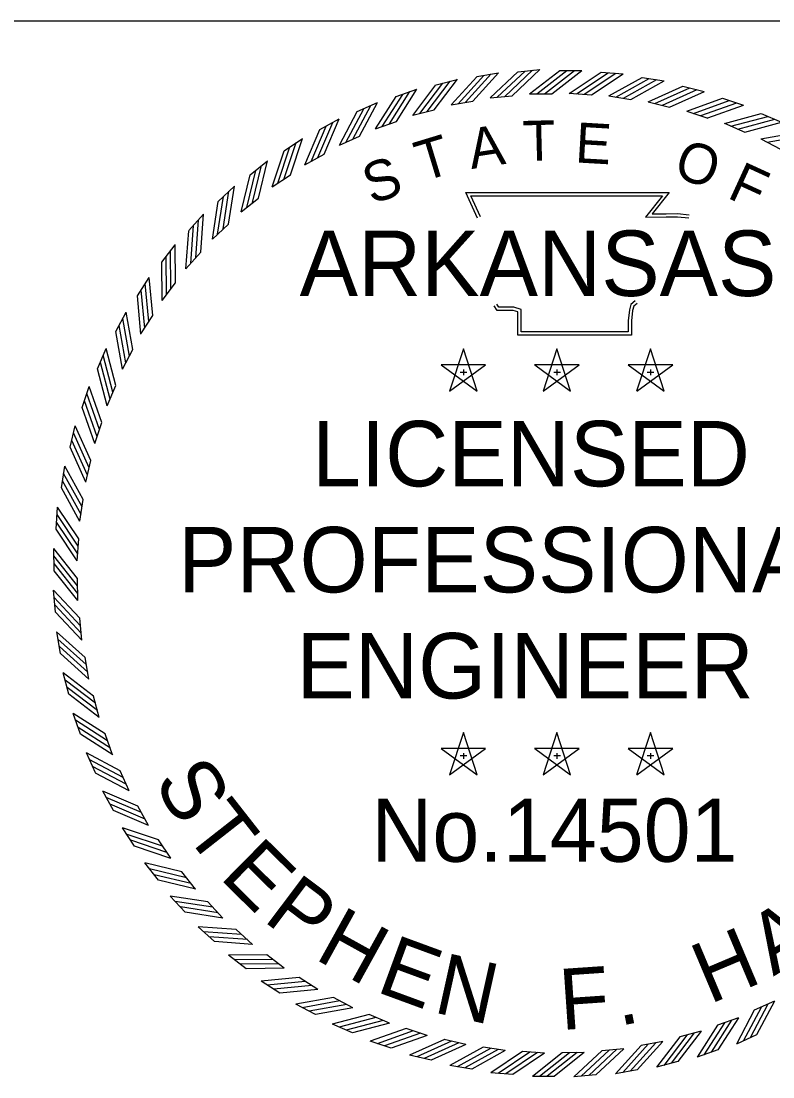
# Model space of a CAD drawing. Extents: x 16 to 1228740, y 11 to 152440.
# Drawn here: x 17.6694 to 17.7979, y 10.8182 to 10.9986 of the extents above; entities that cross this region are included whole.
import ezdxf

# ---------------------------------------------------------------- set-up
doc = ezdxf.new("R2010")
doc.units = 0
doc.layers.add('R_No Plot', color=7, linetype='Continuous')
doc.layers.add('STAMP_FRED', color=7, linetype='Continuous')

msp = doc.modelspace()

# ---------------------------------------------------------------- linework, layer by layer
at = {"layer": 'R_No Plot'}
msp.add_line((17.888, 10.99864), (17.47349, 10.99864), dxfattribs=at)
at = {"layer": 'STAMP_FRED'}
for p, q in [((17.75431, 10.98999), (17.75806, 10.99034)), ((17.74029, 10.98773), (17.74393, 10.98868)), ((17.74725, 10.98915), (17.75096, 10.9898)), ((17.76145, 10.9902), (17.76522, 10.9902)), ((17.76851, 10.98992), (17.77227, 10.98964)), ((17.77555, 10.989), (17.77928, 10.98842)), ((17.73347, 10.98573), (17.73702, 10.98699)), ((17.7825, 10.98751), (17.78616, 10.98662)), ((17.74288, 10.9843), (17.7466, 10.98496)), ((17.74955, 10.98553), (17.75332, 10.98587)), ((17.7563, 10.98619), (17.76008, 10.98619)), ((17.76308, 10.9863), (17.76685, 10.98602)), ((17.76985, 10.98584), (17.77358, 10.98525)), ((17.7893, 10.98545), (17.79288, 10.98426)), ((17.72683, 10.98318), (17.73027, 10.98473)), ((17.73633, 10.98254), (17.73999, 10.9835)), ((17.77655, 10.98483), (17.78023, 10.98394)), ((17.78315, 10.98327), (17.78674, 10.98207)), ((17.72043, 10.9801), (17.72373, 10.98192)), ((17.72996, 10.98024), (17.73352, 10.9815)), ((17.79591, 10.98283), (17.79938, 10.98135)), ((17.7896, 10.98117), (17.79308, 10.97968)), ((17.71431, 10.97649), (17.71745, 10.97858)), ((17.72379, 10.97742), (17.72723, 10.97896)), ((17.79585, 10.97854), (17.79919, 10.97677)), ((17.71787, 10.97409), (17.72118, 10.97592)), ((17.70851, 10.97239), (17.71146, 10.97473)), ((17.71226, 10.9703), (17.7154, 10.97239)), ((17.70306, 10.96782), (17.70581, 10.9704)), ((17.70697, 10.96605), (17.70993, 10.9684)), ((17.69801, 10.96283), (17.70054, 10.96562)), ((17.70205, 10.96138), (17.70481, 10.96396)), ((17.69339, 10.95743), (17.69568, 10.96042)), ((17.69754, 10.95632), (17.70007, 10.95912)), ((17.68923, 10.95166), (17.69126, 10.95484)), ((17.69346, 10.9509), (17.69575, 10.95391)), ((17.68556, 10.94558), (17.68733, 10.94891)), ((17.68984, 10.94517), (17.69187, 10.94835)), ((17.68241, 10.93921), (17.68389, 10.94268)), ((17.6867, 10.93915), (17.68847, 10.94249)), ((17.74497, 10.94264), (17.74261, 10.9354)), ((17.74732, 10.93541), (17.74498, 10.94265)), ((17.76096, 10.94264), (17.7586, 10.9354)), ((17.76331, 10.93541), (17.76097, 10.94265)), ((17.77695, 10.94264), (17.77459, 10.9354)), ((17.7793, 10.93541), (17.77696, 10.94265)), ((17.74877, 10.93988), (17.74116, 10.93988)), ((17.74117, 10.93988), (17.74732, 10.9354)), ((17.74262, 10.93541), (17.74878, 10.93987)), ((17.76476, 10.93988), (17.75715, 10.93988)), ((17.75716, 10.93988), (17.76331, 10.9354)), ((17.75861, 10.93541), (17.76477, 10.93987)), ((17.78076, 10.93988), (17.77315, 10.93988)), ((17.77315, 10.93988), (17.7793, 10.9354)), ((17.7746, 10.93541), (17.78076, 10.93987)), ((17.74443, 10.93866), (17.74556, 10.93866)), ((17.74498, 10.93907), (17.74498, 10.93811)), ((17.76042, 10.93866), (17.76155, 10.93866)), ((17.76097, 10.93907), (17.76097, 10.93811)), ((17.77641, 10.93866), (17.77754, 10.93866)), ((17.77696, 10.93907), (17.77696, 10.93811)), ((17.67979, 10.9326), (17.68098, 10.93618)), ((17.68407, 10.9329), (17.68556, 10.93638)), ((17.67773, 10.9258), (17.67862, 10.92947)), ((17.68197, 10.92645), (17.68317, 10.93004)), ((17.68041, 10.91985), (17.6813, 10.92353)), ((17.67624, 10.91885), (17.67682, 10.92258)), ((17.6794, 10.91315), (17.67999, 10.91688)), ((17.67532, 10.91181), (17.6756, 10.91557)), ((17.67894, 10.90638), (17.67922, 10.91015)), ((17.67499, 10.90471), (17.67496, 10.90848)), ((17.67905, 10.8996), (17.67902, 10.90338)), ((17.67525, 10.89761), (17.6749, 10.90136)), ((17.67972, 10.89285), (17.67937, 10.89662)), ((17.67609, 10.89055), (17.67544, 10.89426)), ((17.68094, 10.88618), (17.68028, 10.8899)), ((17.67751, 10.88359), (17.67656, 10.88724)), ((17.6827, 10.87963), (17.68174, 10.88329)), ((17.67951, 10.87677), (17.67825, 10.88032)), ((17.685, 10.87326), (17.68375, 10.87682)), ((17.74497, 10.87707), (17.74261, 10.86984)), ((17.74732, 10.86984), (17.74498, 10.87708)), ((17.76096, 10.87707), (17.7586, 10.86984)), ((17.76331, 10.86984), (17.76097, 10.87708)), ((17.77695, 10.87707), (17.77459, 10.86984)), ((17.7793, 10.86984), (17.77696, 10.87708)), ((17.68206, 10.87014), (17.68051, 10.87357)), ((17.74877, 10.87431), (17.74116, 10.87432)), ((17.74117, 10.87431), (17.74732, 10.86983)), ((17.74262, 10.86984), (17.74878, 10.87431)), ((17.74443, 10.8731), (17.74556, 10.8731)), ((17.74498, 10.8735), (17.74498, 10.87255)), ((17.76476, 10.87431), (17.75715, 10.87432)), ((17.75716, 10.87431), (17.76331, 10.86983)), ((17.75861, 10.86984), (17.76477, 10.87431)), ((17.76042, 10.8731), (17.76155, 10.8731)), ((17.76097, 10.8735), (17.76097, 10.87255)), ((17.78076, 10.87431), (17.77315, 10.87432)), ((17.77315, 10.87431), (17.7793, 10.86983)), ((17.7746, 10.86984), (17.78076, 10.87431)), ((17.77641, 10.8731), (17.77754, 10.8731)), ((17.77696, 10.8735), (17.77696, 10.87255)), ((17.68783, 10.86709), (17.68628, 10.87053)), ((17.68515, 10.86374), (17.68332, 10.86703)), ((17.69115, 10.86118), (17.68932, 10.86448)), ((17.68875, 10.85761), (17.68666, 10.86075)), ((17.69494, 10.85556), (17.69285, 10.8587)), ((17.69285, 10.85181), (17.69051, 10.85476)), ((17.69919, 10.85027), (17.69684, 10.85323)), ((17.69742, 10.84636), (17.69484, 10.84911)), ((17.70386, 10.84535), (17.70128, 10.84811)), ((17.70242, 10.84131), (17.69962, 10.84384)), ((17.70892, 10.84084), (17.70612, 10.84337)), ((17.70781, 10.83669), (17.70482, 10.83898)), ((17.71434, 10.83676), (17.71134, 10.83905)), ((17.72007, 10.83314), (17.71689, 10.83517)), ((17.71358, 10.83253), (17.7104, 10.83456)), ((17.72609, 10.83), (17.72275, 10.83177)), ((17.71966, 10.82886), (17.71633, 10.83063)), ((17.79815, 10.83113), (17.79471, 10.82958)), ((17.73234, 10.82738), (17.72886, 10.82886)), ((17.79199, 10.82831), (17.78842, 10.82705)), ((17.72603, 10.82571), (17.72257, 10.82719)), ((17.73879, 10.82527), (17.7352, 10.82647)), ((17.74539, 10.82371), (17.74171, 10.82461)), ((17.78561, 10.826), (17.78195, 10.82504)), ((17.79511, 10.82536), (17.79167, 10.82381)), ((17.73264, 10.82309), (17.72906, 10.82428)), ((17.75209, 10.8227), (17.74836, 10.82329)), ((17.75886, 10.82224), (17.75509, 10.82252)), ((17.77239, 10.82302), (17.76863, 10.82267)), ((17.77906, 10.82424), (17.77534, 10.82358)), ((17.78847, 10.82281), (17.78492, 10.82155)), ((17.73944, 10.82103), (17.73578, 10.82192)), ((17.76564, 10.82235), (17.76186, 10.82232)), ((17.78165, 10.82082), (17.77801, 10.81986)), ((17.74639, 10.81954), (17.74266, 10.82012)), ((17.75343, 10.81862), (17.74967, 10.8189)), ((17.77469, 10.81939), (17.77098, 10.81874)), ((17.76053, 10.81829), (17.75676, 10.81826)), ((17.76763, 10.81855), (17.76388, 10.8182))]:
    msp.add_line(p, q, dxfattribs=at)
for points in [[(17.75331, 10.98587), (17.75806, 10.99034)], [(17.73998, 10.9835), (17.74394, 10.98869)], [(17.74288, 10.9843), (17.74725, 10.98914)], [(17.74407, 10.9845), (17.74844, 10.98934)], [(17.74536, 10.98476), (17.74973, 10.9896)], [(17.7466, 10.98496), (17.75097, 10.98981)], [(17.74955, 10.98552), (17.7543, 10.98999)], [(17.75076, 10.98562), (17.75551, 10.99009)], [(17.75206, 10.98577), (17.75681, 10.99024)], [(17.7563, 10.98619), (17.76144, 10.9902)], [(17.75751, 10.98618), (17.76265, 10.99019)], [(17.75882, 10.9862), (17.76396, 10.99022)], [(17.76008, 10.98619), (17.76522, 10.9902)], [(17.76308, 10.98629), (17.7685, 10.98992)], [(17.76429, 10.98619), (17.76971, 10.98982)], [(17.7656, 10.98613), (17.77102, 10.98975)], [(17.76685, 10.98602), (17.77227, 10.98964)], [(17.76984, 10.98584), (17.77555, 10.989)], [(17.77104, 10.98564), (17.77675, 10.9888)], [(17.77234, 10.98546), (17.77804, 10.98863)], [(17.73351, 10.9815), (17.73702, 10.98699)], [(17.73633, 10.98253), (17.74028, 10.98772)], [(17.73751, 10.98283), (17.74146, 10.98802)], [(17.73877, 10.98319), (17.74272, 10.98838)], [(17.77358, 10.98526), (17.77928, 10.98842)], [(17.77655, 10.98483), (17.7825, 10.98751)], [(17.77773, 10.98453), (17.78367, 10.98721)], [(17.779, 10.98425), (17.78495, 10.98693)], [(17.72995, 10.98023), (17.73346, 10.98573)], [(17.7311, 10.98063), (17.73461, 10.98612)], [(17.73232, 10.98109), (17.73584, 10.98659)], [(17.78022, 10.98394), (17.78617, 10.98662)], [(17.78315, 10.98327), (17.7893, 10.98545)], [(17.7843, 10.98287), (17.79044, 10.98505)], [(17.72379, 10.97741), (17.72683, 10.98318)], [(17.7249, 10.9779), (17.72794, 10.98367)], [(17.72608, 10.97846), (17.72912, 10.98423)], [(17.72723, 10.97897), (17.73028, 10.98473)], [(17.78555, 10.98249), (17.7917, 10.98467)], [(17.78674, 10.98208), (17.79288, 10.98426)], [(17.72007, 10.97533), (17.72263, 10.98133)], [(17.72118, 10.97592), (17.72374, 10.98192)], [(17.7896, 10.98116), (17.7959, 10.98283)], [(17.79071, 10.98068), (17.79701, 10.98234)], [(17.79192, 10.98019), (17.79823, 10.98185)], [(17.79307, 10.97968), (17.79938, 10.98135)], [(17.71787, 10.97409), (17.72043, 10.98009)], [(17.71894, 10.97467), (17.7215, 10.98067)], [(17.79585, 10.97854), (17.80227, 10.97968)], [(17.71434, 10.97171), (17.7164, 10.9779)], [(17.71539, 10.97239), (17.71745, 10.97858)], [(17.79692, 10.97796), (17.80334, 10.9791)], [(17.71225, 10.97029), (17.71431, 10.97648)], [(17.71327, 10.97096), (17.71532, 10.97715)], [(17.70992, 10.9684), (17.71146, 10.97474)], [(17.70697, 10.96604), (17.70851, 10.97238)], [(17.70793, 10.96679), (17.70946, 10.97313)], [(17.70893, 10.96763), (17.71047, 10.97396)], [(17.70294, 10.9622), (17.70395, 10.96864)], [(17.70388, 10.96311), (17.70489, 10.96956)], [(17.7048, 10.96396), (17.70581, 10.97041)], [(17.7474, 10.96497), (17.74539, 10.96932), (17.78016, 10.96934), (17.77725, 10.96569), (17.77962, 10.96572), (17.78159, 10.96575), (17.78356, 10.96553)], [(17.7479, 10.9652), (17.74625, 10.96877), (17.77902, 10.96879), (17.7761, 10.96513), (17.77962, 10.96517), (17.78156, 10.9652), (17.7835, 10.96499)], [(17.70205, 10.96137), (17.70306, 10.96782)], [(17.70007, 10.95912), (17.70054, 10.96563)], [(17.69836, 10.95721), (17.69883, 10.96371)], [(17.69922, 10.9582), (17.69969, 10.9647)], [(17.69754, 10.95631), (17.69801, 10.96282)], [(17.69574, 10.9539), (17.69568, 10.96043)], [(17.6942, 10.95185), (17.69414, 10.95838)], [(17.69497, 10.95291), (17.69491, 10.95944)], [(17.69346, 10.9509), (17.69339, 10.95742)], [(17.69187, 10.94835), (17.69126, 10.95484)], [(17.6905, 10.94618), (17.6899, 10.95267)], [(17.69118, 10.9473), (17.69058, 10.95379)], [(17.68984, 10.94516), (17.68923, 10.95166)], [(17.77433, 10.95083), (17.7736, 10.95023), (17.77335, 10.9493), (17.77314, 10.94742), (17.77314, 10.94554), (17.75484, 10.94554), (17.75484, 10.94824), (17.75484, 10.94936), (17.75358, 10.94975), (17.75104, 10.94975), (17.75071, 10.95025)], [(17.68847, 10.94249), (17.68733, 10.94891)], [(17.77468, 10.9504), (17.77409, 10.94992), (17.77389, 10.9492), (17.77369, 10.94739), (17.77369, 10.94499), (17.75429, 10.94499), (17.75429, 10.94824), (17.75429, 10.94896), (17.7535, 10.9492), (17.75074, 10.9492), (17.75025, 10.94995)], [(17.68787, 10.94139), (17.68673, 10.94781)], [(17.6867, 10.93915), (17.68556, 10.94557)], [(17.68728, 10.94022), (17.68614, 10.94664)], [(17.68556, 10.93637), (17.68389, 10.94268)], [(17.68456, 10.93401), (17.6829, 10.94031)], [(17.68505, 10.93522), (17.68339, 10.94153)], [(17.68408, 10.9329), (17.68241, 10.9392)], [(17.68316, 10.93004), (17.68098, 10.93618)], [(17.68276, 10.92885), (17.68057, 10.935)], [(17.68197, 10.92645), (17.67979, 10.9326)], [(17.68237, 10.9276), (17.68019, 10.93374)], [(17.6813, 10.92352), (17.67862, 10.92947)], [(17.68099, 10.92231), (17.67831, 10.92825)], [(17.68041, 10.91985), (17.67773, 10.9258)], [(17.68071, 10.92103), (17.67803, 10.92697)], [(17.67998, 10.91688), (17.67682, 10.92258)], [(17.6796, 10.91434), (17.67644, 10.92005)], [(17.67978, 10.91564), (17.67661, 10.92134)], [(17.6794, 10.91314), (17.67624, 10.91885)], [(17.67922, 10.91015), (17.6756, 10.91557)], [(17.67905, 10.90759), (17.67542, 10.91301)], [(17.67912, 10.9089), (17.67549, 10.91432)], [(17.67895, 10.90638), (17.67532, 10.9118)], [(17.67901, 10.90338), (17.67495, 10.90848)], [(17.67901, 10.90212), (17.67495, 10.90723)], [(17.67905, 10.90081), (17.675, 10.90592)], [(17.67905, 10.8996), (17.675, 10.9047)], [(17.67937, 10.89661), (17.6749, 10.90136)], [(17.67947, 10.89536), (17.675, 10.90011)], [(17.67962, 10.89406), (17.67515, 10.89881)], [(17.67972, 10.89285), (17.67525, 10.8976)], [(17.68028, 10.8899), (17.67543, 10.89427)], [(17.68048, 10.88866), (17.67564, 10.89303)], [(17.68074, 10.88738), (17.6759, 10.89174)], [(17.68094, 10.88618), (17.6761, 10.89055)], [(17.68174, 10.88328), (17.67655, 10.88724)], [(17.68205, 10.88207), (17.67686, 10.88602)], [(17.68241, 10.88081), (17.67722, 10.88476)], [(17.68271, 10.87963), (17.67752, 10.88359)], [(17.68374, 10.87681), (17.67825, 10.88032)], [(17.68415, 10.87563), (17.67865, 10.87914)], [(17.68462, 10.8744), (17.67912, 10.87791)], [(17.68501, 10.87325), (17.67951, 10.87676)], [(17.68628, 10.87053), (17.68051, 10.87358)], [(17.68678, 10.86938), (17.68101, 10.87243)], [(17.68734, 10.8682), (17.68158, 10.87124)], [(17.68783, 10.86709), (17.68206, 10.87013)], [(17.68932, 10.86448), (17.68332, 10.86704)], [(17.68991, 10.86337), (17.68391, 10.86593)], [(17.69057, 10.86224), (17.68457, 10.8648)], [(17.69115, 10.86117), (17.68515, 10.86373)], [(17.69285, 10.8587), (17.68666, 10.86075)], [(17.69353, 10.85764), (17.68734, 10.8597)], [(17.69428, 10.85657), (17.68809, 10.85863)], [(17.69495, 10.85555), (17.68876, 10.85761)], [(17.69684, 10.85323), (17.6905, 10.85476)], [(17.69762, 10.85223), (17.69128, 10.85377)], [(17.69845, 10.85123), (17.69211, 10.85276)], [(17.6992, 10.85027), (17.69286, 10.85181)], [(17.70128, 10.8481), (17.69483, 10.84911)], [(17.70213, 10.84718), (17.69568, 10.84819)], [(17.70305, 10.84624), (17.6966, 10.84725)], [(17.70387, 10.84535), (17.69742, 10.84636)], [(17.70612, 10.84337), (17.69961, 10.84384)], [(17.70704, 10.84252), (17.70054, 10.84299)], [(17.70804, 10.84166), (17.70153, 10.84213)], [(17.70893, 10.84084), (17.70242, 10.84131)], [(17.71134, 10.83905), (17.70481, 10.83898)], [(17.71233, 10.83827), (17.70581, 10.83821)], [(17.71339, 10.8375), (17.70686, 10.83744)], [(17.71434, 10.83676), (17.70782, 10.83669)], [(17.71689, 10.83517), (17.7104, 10.83456)], [(17.71794, 10.83448), (17.71145, 10.83388)], [(17.71906, 10.8338), (17.71257, 10.8332)], [(17.72008, 10.83314), (17.71358, 10.83253)], [(17.72275, 10.83177), (17.71633, 10.83063)], [(17.72385, 10.83117), (17.71743, 10.83003)], [(17.72503, 10.83058), (17.7186, 10.82944)], [(17.72609, 10.83), (17.71967, 10.82886)], [(17.79586, 10.83008), (17.79282, 10.82431)], [(17.79704, 10.83064), (17.794, 10.82488)], [(17.79816, 10.83113), (17.79511, 10.82536)], [(17.72887, 10.82886), (17.72256, 10.82719)], [(17.73002, 10.82835), (17.72371, 10.82669)], [(17.79084, 10.82792), (17.78733, 10.82242)], [(17.79199, 10.82831), (17.78848, 10.82281)], [(17.79471, 10.82958), (17.79167, 10.82381)], [(17.73123, 10.82786), (17.72493, 10.8262)], [(17.73234, 10.82738), (17.72604, 10.82571)], [(17.7352, 10.82646), (17.72906, 10.82428)], [(17.78843, 10.82704), (17.78492, 10.82155)], [(17.78962, 10.82745), (17.7861, 10.82196)], [(17.73639, 10.82606), (17.73025, 10.82387)], [(17.73764, 10.82567), (17.7315, 10.82349)], [(17.73879, 10.82528), (17.73264, 10.82309)], [(17.74172, 10.8246), (17.73577, 10.82192)], [(17.74294, 10.82429), (17.73699, 10.82161)], [(17.78196, 10.82504), (17.778, 10.81985)], [(17.78317, 10.82535), (17.77922, 10.82016)], [(17.78443, 10.82571), (17.78048, 10.82052)], [(17.78561, 10.82601), (17.78166, 10.82082)], [(17.74421, 10.82401), (17.73827, 10.82133)], [(17.74539, 10.82371), (17.73944, 10.82103)], [(17.74836, 10.82328), (17.74266, 10.82012)], [(17.7496, 10.82308), (17.7439, 10.81991)], [(17.7509, 10.8229), (17.74519, 10.81974)], [(17.7521, 10.8227), (17.74639, 10.81954)], [(17.75509, 10.82252), (17.74967, 10.8189)], [(17.76863, 10.82267), (17.76388, 10.8182)], [(17.76988, 10.82277), (17.76513, 10.8183)], [(17.77118, 10.82292), (17.76643, 10.81845)], [(17.77239, 10.82302), (17.76764, 10.81855)], [(17.77534, 10.82358), (17.77097, 10.81873)], [(17.77658, 10.82379), (17.77221, 10.81894)], [(17.77787, 10.82404), (17.7735, 10.8192)], [(17.77906, 10.82424), (17.77469, 10.8194)], [(17.75635, 10.82242), (17.75092, 10.81879)], [(17.75765, 10.82235), (17.75223, 10.81873)], [(17.75886, 10.82225), (17.75344, 10.81862)], [(17.76186, 10.82231), (17.75676, 10.81825)], [(17.76312, 10.82231), (17.75801, 10.81825)], [(17.76443, 10.82235), (17.75932, 10.8183)], [(17.76564, 10.82235), (17.76054, 10.8183)]]:
    msp.add_lwpolyline(points, dxfattribs=at)

# ---------------------------------------------------------------- texts
for s, height, rotation, p in [('T', 0.00686, 1.4789, (17.7552, 10.97471)), ('E', 0.00686, 356.672, (17.76397, 10.9745)), ('A', 0.00686, 8.6788, (17.74634, 10.97334)), ('T', 0.00686, 16.9015, (17.73801, 10.97117)), ('O', 0.00686, 341.2218, (17.78063, 10.97215)), ('S', 0.00686, 19.7726, (17.72929, 10.96725)), ('F', 0.00686, 335.3628, (17.78987, 10.96853)), ('S', 0.01042, 300.7985, (17.69188, 10.86863)), ('T', 0.01042, 308.0945, (17.69697, 10.8601)), ('E', 0.01042, 315.3905, (17.7031, 10.85228)), ('P', 0.01042, 323.0513, (17.71054, 10.84498)), ('H', 0.01042, 331.0769, (17.71932, 10.83847)), ('A', 0.01042, 31.6338, (17.79797, 10.83533)), ('H', 0.01042, 22.8786, (17.78705, 10.83056)), ('E', 0.01042, 339.8321, (17.72982, 10.83284)), ('N', 0.01042, 347.4929, (17.73962, 10.82928)), ('F', 0.01042, 3.9089, (17.7617, 10.8262)), ('.', 0.01042, 11.205, (17.77161, 10.82688))]:
    msp.add_text(s, height=height, rotation=rotation, dxfattribs=at).set_placement(p)
for s, height, p in [('ARKANSAS', 0.011193, (17.71697, 10.95165)), ('LICENSED', 0.011193, (17.7191, 10.91912)), ('PROFESSIONAL', 0.0111934, (17.69618, 10.901)), ('ENGINEER', 0.011193, (17.71644, 10.88287)), ('No.14501', 0.010794, (17.72924, 10.85496))]:
    msp.add_text(s, height=height, dxfattribs=at).set_placement(p)

doc.saveas('drawing.dxf')
